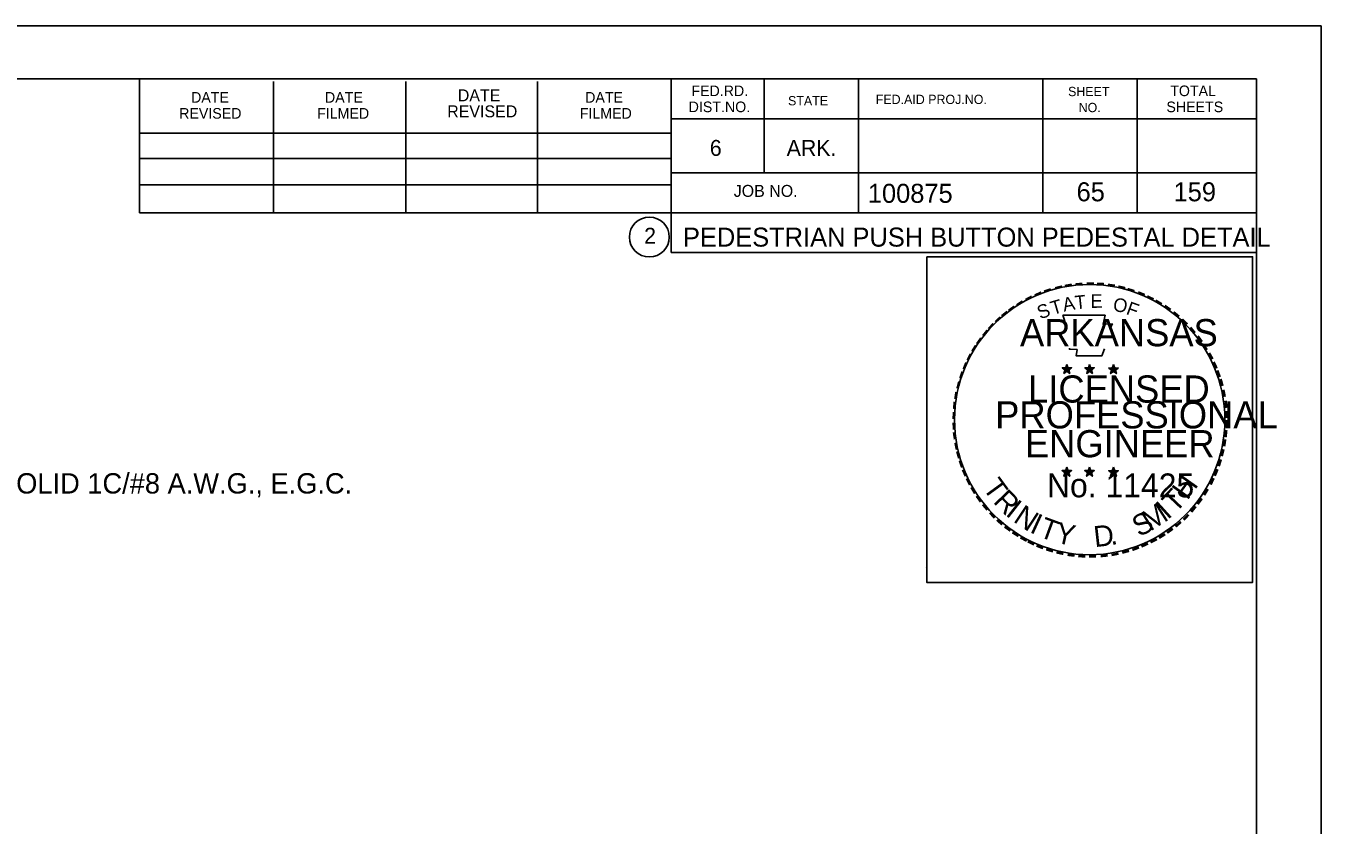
# Model space of a CAD drawing. Extents: x 1369885 to 1370886, y 379976 to 380616.
# Drawn here: x 1370599.4 to 1370885.5, y 380438.9 to 380615.6 of the extents above; entities that cross this region are included whole.
import ezdxf

# ---------------------------------------------------------------- set-up
doc = ezdxf.new("R2010")
doc.units = 0
for name, color, linetype in [('R_Border', 7, 'Continuous'), ('R_Border PE', 7, 'Continuous'), ('R_Draft', 7, 'Continuous'), ('R_No Plot', 7, 'Continuous')]:
    doc.layers.add(name, color=color, linetype=linetype)

msp = doc.modelspace()

# ---------------------------------------------------------------- linework, layer by layer
at = {"layer": 'R_Border'}
for p, q in [((1369922.71, 380603.9), (1370871.25, 380603.9)), ((1370624.47, 380574.26), (1370624.47, 380603.9)), ((1370654.05, 380574.26), (1370654.05, 380603.3)), ((1370683.33, 380574.26), (1370683.33, 380603.3)), ((1370712.37, 380574.26), (1370712.37, 380603.3)), ((1370741.95, 380603.9), (1370741.95, 380565.5)), ((1370762.47, 380603.9), (1370762.47, 380583.08)), ((1370783.29, 380603.9), (1370783.29, 380574.26)), ((1370824.03, 380603.9), (1370824.03, 380574.26)), ((1370844.85, 380603.9), (1370844.85, 380574.26)), ((1370871.25, 379987.52), (1370871.25, 380603.9)), ((1370871.25, 380595.08), (1370741.95, 380595.08)), ((1370871.25, 380595.14), (1370871.25, 380595.14)), ((1370624.47, 380591.84), (1370741.95, 380591.84)), ((1370624.47, 380586.26), (1370741.95, 380586.26)), ((1370871.25, 380583.08), (1370741.95, 380583.08)), ((1370750.83, 380583.08), (1370871.25, 380583.08)), ((1370624.47, 380574.26), (1370624.47, 380580.44)), ((1370624.47, 380580.44), (1370741.95, 380580.44)), ((1370871.25, 380574.26), (1370624.47, 380574.26)), ((1370741.95, 380565.5), (1370871.25, 380565.5))]:
    msp.add_line(p, q, dxfattribs=at)
msp.add_circle((1370737.11, 380568.91), 4.4, dxfattribs=at)
at = {"layer": 'R_Border PE'}
for p, q in [((1370828.31, 380540.01), (1370829.35, 380539.67)), ((1370828.31, 380540.01), (1370829.07, 380539.87)), ((1370828.31, 380540.01), (1370829.02, 380539.64)), ((1370828.71, 380538.78), (1370829.35, 380539.67)), ((1370828.71, 380538.78), (1370829.08, 380539.51)), ((1370828.71, 380538.78), (1370829.35, 380539.43)), ((1370829.35, 380540.77), (1370829.23, 380540.01)), ((1370829.35, 380539.67), (1370829.35, 380540.77)), ((1370829.35, 380540.77), (1370829.5, 380540.02)), ((1370830.39, 380540.01), (1370829.35, 380539.67)), ((1370829.99, 380538.78), (1370829.35, 380539.67)), ((1370829.99, 380538.78), (1370829.35, 380539.42)), ((1370830.39, 380540.01), (1370829.54, 380539.86)), ((1370829.99, 380538.78), (1370829.58, 380539.66)), ((1370830.39, 380540.01), (1370829.78, 380539.7)), ((1370833.32, 380540.01), (1370834.36, 380539.67)), ((1370833.32, 380540.01), (1370834.08, 380539.87)), ((1370833.32, 380540.01), (1370834.03, 380539.64)), ((1370833.72, 380538.78), (1370834.36, 380539.67)), ((1370833.72, 380538.78), (1370834.09, 380539.51)), ((1370833.72, 380538.78), (1370834.36, 380539.43)), ((1370834.36, 380540.77), (1370834.24, 380540.01)), ((1370834.36, 380539.67), (1370834.36, 380540.77)), ((1370834.36, 380540.77), (1370834.51, 380540.02)), ((1370835.4, 380540.01), (1370834.36, 380539.67)), ((1370835, 380538.78), (1370834.36, 380539.67)), ((1370835, 380538.78), (1370834.36, 380539.42)), ((1370835.4, 380540.01), (1370834.55, 380539.86)), ((1370835, 380538.78), (1370834.59, 380539.66)), ((1370835.4, 380540.01), (1370834.79, 380539.7)), ((1370838.61, 380539.97), (1370839.66, 380539.64)), ((1370838.61, 380539.97), (1370839.37, 380539.84)), ((1370838.61, 380539.97), (1370839.32, 380539.6)), ((1370839.01, 380538.75), (1370839.66, 380539.64)), ((1370839.01, 380538.75), (1370839.39, 380539.48)), ((1370839.01, 380538.75), (1370839.65, 380539.4)), ((1370839.66, 380540.73), (1370839.53, 380539.98)), ((1370840.29, 380538.75), (1370839.65, 380539.39)), ((1370839.66, 380539.64), (1370839.66, 380540.73)), ((1370839.66, 380540.73), (1370839.8, 380539.98)), ((1370840.7, 380539.97), (1370839.66, 380539.64)), ((1370840.29, 380538.75), (1370839.66, 380539.64)), ((1370840.7, 380539.97), (1370839.84, 380539.82)), ((1370840.29, 380538.75), (1370839.88, 380539.62)), ((1370840.7, 380539.97), (1370840.08, 380539.66)), ((1370828.29, 380517.29), (1370829.34, 380516.95)), ((1370828.29, 380517.29), (1370829.05, 380517.15)), ((1370828.29, 380517.29), (1370829.01, 380516.92)), ((1370828.69, 380516.06), (1370829.34, 380516.95)), ((1370828.69, 380516.06), (1370829.07, 380516.8)), ((1370828.69, 380516.06), (1370829.34, 380516.71)), ((1370829.34, 380518.05), (1370829.22, 380517.29)), ((1370829.34, 380516.95), (1370829.34, 380518.05)), ((1370829.34, 380518.05), (1370829.49, 380517.3)), ((1370830.38, 380517.29), (1370829.34, 380516.95)), ((1370829.98, 380516.06), (1370829.34, 380516.95)), ((1370829.98, 380516.06), (1370829.34, 380516.71)), ((1370830.38, 380517.29), (1370829.52, 380517.14)), ((1370829.98, 380516.06), (1370829.57, 380516.94)), ((1370830.38, 380517.29), (1370829.77, 380516.98)), ((1370833.3, 380517.29), (1370834.35, 380516.95)), ((1370833.3, 380517.29), (1370834.06, 380517.15)), ((1370833.3, 380517.29), (1370834.01, 380516.92)), ((1370833.7, 380516.06), (1370834.35, 380516.95)), ((1370833.7, 380516.06), (1370834.08, 380516.8)), ((1370833.7, 380516.06), (1370834.34, 380516.71)), ((1370834.35, 380518.05), (1370834.23, 380517.29)), ((1370834.99, 380516.06), (1370834.34, 380516.71)), ((1370834.35, 380516.95), (1370834.35, 380518.05)), ((1370834.35, 380518.05), (1370834.5, 380517.3)), ((1370835.39, 380517.29), (1370834.35, 380516.95)), ((1370834.99, 380516.06), (1370834.35, 380516.95)), ((1370835.39, 380517.29), (1370834.53, 380517.14)), ((1370834.99, 380516.06), (1370834.58, 380516.94)), ((1370835.39, 380517.29), (1370834.78, 380516.98)), ((1370838.6, 380517.26), (1370839.65, 380516.92)), ((1370838.6, 380517.26), (1370839.36, 380517.12)), ((1370838.6, 380517.26), (1370839.31, 380516.89)), ((1370839, 380516.03), (1370839.65, 380516.92)), ((1370839, 380516.03), (1370839.38, 380516.77)), ((1370839, 380516.03), (1370839.64, 380516.68)), ((1370839.65, 380518.02), (1370839.53, 380517.26)), ((1370840.29, 380516.03), (1370839.64, 380516.68)), ((1370839.65, 380516.92), (1370839.65, 380518.02)), ((1370839.65, 380518.02), (1370839.8, 380517.27)), ((1370840.69, 380517.26), (1370839.65, 380516.92)), ((1370840.29, 380516.03), (1370839.65, 380516.92)), ((1370840.69, 380517.26), (1370839.83, 380517.11)), ((1370840.29, 380516.03), (1370839.88, 380516.91)), ((1370840.69, 380517.26), (1370840.08, 380516.95))]:
    msp.add_line(p, q, dxfattribs=at)
for points in [[(1370828.43, 380551.64), (1370829.24, 380549.16)], [(1370838.96, 380548.87), (1370839.39, 380549.73), (1370837.33, 380549.65), (1370837.78, 380551.64), (1370828.43, 380551.64)], [(1370829.91, 380544.37), (1370829.91, 380544.11), (1370831.59, 380544.05), (1370831.43, 380542.63), (1370837.04, 380542.63), (1370837.65, 380544.24)], [(1370829.35, 380540.77), (1370829.99, 380538.78), (1370828.31, 380540.01), (1370830.39, 380540.01), (1370828.71, 380538.78), (1370829.35, 380540.77)], [(1370834.36, 380540.77), (1370835, 380538.78), (1370833.32, 380540.01), (1370835.4, 380540.01), (1370833.72, 380538.78), (1370834.36, 380540.77)], [(1370839.66, 380540.73), (1370840.29, 380538.75), (1370838.61, 380539.97), (1370840.7, 380539.97), (1370839.01, 380538.75), (1370839.66, 380540.73)], [(1370829.34, 380518.05), (1370829.98, 380516.06), (1370828.29, 380517.29), (1370830.38, 380517.29), (1370828.69, 380516.06), (1370829.34, 380518.05)], [(1370834.35, 380518.05), (1370834.99, 380516.06), (1370833.3, 380517.29), (1370835.39, 380517.29), (1370833.7, 380516.06), (1370834.35, 380518.05)], [(1370839.65, 380518.02), (1370840.29, 380516.03), (1370838.6, 380517.26), (1370840.69, 380517.26), (1370839, 380516.03), (1370839.65, 380518.02)]]:
    msp.add_lwpolyline(points, dxfattribs=at)
for centre, radius in [((1370829.35, 380539.67), 0.517), ((1370829.35, 380539.67), 0.434), ((1370829.35, 380539.67), 0.347), ((1370829.35, 380539.67), 0.297), ((1370829.35, 380539.67), 0.224), ((1370829.35, 380539.67), 0.149), ((1370829.35, 380539.67), 0.0889), ((1370834.36, 380539.67), 0.517), ((1370834.36, 380539.67), 0.434), ((1370834.36, 380539.67), 0.347), ((1370834.36, 380539.67), 0.297), ((1370834.36, 380539.67), 0.224), ((1370834.36, 380539.67), 0.149), ((1370834.36, 380539.67), 0.0889), ((1370839.65, 380539.64), 0.517), ((1370839.65, 380539.64), 0.434), ((1370839.65, 380539.64), 0.347), ((1370839.65, 380539.64), 0.297), ((1370839.65, 380539.64), 0.224), ((1370839.65, 380539.64), 0.149), ((1370839.65, 380539.64), 0.0889), ((1370829.34, 380516.95), 0.517), ((1370829.34, 380516.95), 0.434), ((1370829.34, 380516.95), 0.347), ((1370829.34, 380516.95), 0.297), ((1370829.34, 380516.95), 0.224), ((1370829.34, 380516.95), 0.149), ((1370829.34, 380516.95), 0.0889), ((1370834.35, 380516.95), 0.517), ((1370834.35, 380516.95), 0.434), ((1370834.35, 380516.95), 0.347), ((1370834.35, 380516.95), 0.297), ((1370834.35, 380516.95), 0.224), ((1370834.35, 380516.95), 0.149), ((1370834.35, 380516.95), 0.0889), ((1370839.65, 380516.92), 0.517), ((1370839.65, 380516.92), 0.434), ((1370839.65, 380516.92), 0.347), ((1370839.65, 380516.92), 0.297), ((1370839.65, 380516.92), 0.224), ((1370839.65, 380516.92), 0.149), ((1370839.65, 380516.92), 0.0889)]:
    msp.add_circle(centre, radius, dxfattribs=at)
at = {"layer": 'R_No Plot'}
for p, q in [((1369885.51, 380615.59), (1370885.51, 380615.59)), ((1370798.15, 380495.87), (1370798.15, 380495.87))]:
    msp.add_line(p, q, dxfattribs=at)
for points in [[(1369885.49, 380615.59), (1370885.51, 380615.59), (1370885.51, 379975.58), (1369885.49, 379975.58)], [(1370798.39, 380564.56), (1370870.39, 380564.56), (1370870.39, 380492.56), (1370798.39, 380492.56)]]:
    msp.add_lwpolyline(points, close=True, dxfattribs=at)
msp.add_circle((1370834.39, 380528.56), 29.86, dxfattribs=at)

# ---------------------------------------------------------------- texts
at = {"layer": 'R_Border'}
for s, height, p in [('DATE', 2.638, (1370694.79, 380598.92)), ('FED.RD.', 2.346, (1370746.39, 380600.06)), ('SHEET', 2.052, (1370829.61, 380600.06)), ('TOTAL', 2.346, (1370852.17, 380600.06)), ('DATE', 2.346, (1370635.87, 380598.62)), ('DATE', 2.346, (1370665.45, 380598.62)), ('DATE', 2.346, (1370722.93, 380598.62)), ('DIST.NO.', 2.346, (1370745.79, 380596.52)), ('STATE', 2.052, (1370767.75, 380598.02)), ('FED.AID PROJ.NO.', 2.052, (1370787.13, 380598.32)), ('NO.', 2.052, (1370831.95, 380596.52)), ('SHEETS', 2.346, (1370851.33, 380596.52)), ('REVISED', 2.346, (1370633.23, 380595.08)), ('FILMED', 2.346, (1370663.71, 380595.08)), ('REVISED', 2.638, (1370692.45, 380595.38)), ('FILMED', 2.346, (1370721.73, 380595.08)), ('6', 3.52, (1370750.47, 380586.86)), ('ARK.', 3.517, (1370767.45, 380586.86)), ('JOB NO.', 2.638, (1370755.75, 380577.8)), ('100875', 4.2, (1370785.38, 380576.48)), ('65', 4.2, (1370831.49, 380576.82)), ('159', 4.2, (1370852.92, 380576.82)), ('2', 3.52, (1370735.96, 380567.45)), ('PEDESTRIAN PUSH BUTTON PEDESTAL DETAIL', 4.2, (1370744.54, 380566.8))]:
    msp.add_text(s, height=height, dxfattribs=at).set_placement(p)
at = {"layer": 'R_Border PE'}
for s, height, rotation, p in [('-', 4.8, 10.2193, (1370828.96, 380556.23)), ('-', 4.8, 5.8968, (1370831.14, 380556.56)), ('-', 4.8, 0.1862, (1370833.46, 380556.78)), ('-', 4.8, 357.743, (1370835.63, 380556.74)), ('-', 4.8, 352.1617, (1370837.86, 380556.57)), ('-', 4.8, 28.7918, (1370820.87, 380553.26)), ('-', 4.8, 24.3072, (1370822.77, 380554.21)), ('-', 4.8, 19.1761, (1370824.67, 380555.02)), ('-', 4.8, 13.6302, (1370826.92, 380555.74)), ('A', 3, 11.2132, (1370828.71, 380552.42)), ('T', 3, 6.0228, (1370831.26, 380552.92)), ('E', 3, 0.8323, (1370834.58, 380553.25)), ('-', 4.8, 347.2049, (1370840.02, 380556.23)), ('-', 4.8, 342.3362, (1370841.92, 380555.76)), ('-', 4.8, 337.8551, (1370844.13, 380555.09)), ('-', 4.8, 334.1211, (1370846.02, 380554.28)), ('-', 4.8, 38.9507, (1370815.92, 380549.83)), ('-', 4.8, 36.2317, (1370817.35, 380550.97)), ('-', 4.8, 34.0636, (1370819.08, 380552.15)), ('S', 3, 21.594, (1370823.49, 380550.67)), ('T', 3, 16.4036, (1370826.24, 380551.67)), ('O', 3, 350.4515, (1370839.39, 380552.62)), ('F', 3, 340.0707, (1370842.25, 380551.93)), ('-', 4.8, 329.6409, (1370847.76, 380553.43)), ('-', 4.8, 325.8627, (1370849.69, 380552.35)), ('-', 4.8, 48.4231, (1370813.28, 380547.15)), ('-', 4.8, 42.9622, (1370814.62, 380548.58)), ('-', 4.8, 320.5297, (1370851.52, 380551.07)), ('-', 4.8, 315.5786, (1370853.31, 380549.61)), ('-', 4.8, 50.6142, (1370812.07, 380545.69)), ('-', 4.8, 309.8797, (1370855.02, 380547.96)), ('-', 4.8, 306.6522, (1370856.6, 380546.15)), ('-', 4.8, 58.0706, (1370809.85, 380542.41)), ('-', 4.8, 54.2325, (1370810.83, 380543.99)), ('-', 4.2, 303.6753, (1370858.05, 380544.45)), ('-', 4.8, 67.7743, (1370808.14, 380538.73)), ('-', 4.8, 62.8713, (1370808.91, 380540.57)), ('-', 4.8, 299.6684, (1370859.01, 380542.63)), ('-', 4.8, 294.6628, (1370859.98, 380540.79)), ('-', 4.8, 72.3945, (1370807.48, 380536.84)), ('-', 4.8, 290.5728, (1370860.75, 380539.06)), ('-', 4.8, 75.461, (1370806.89, 380534.7)), ('-', 4.8, 285.1233, (1370861.46, 380537.32)), ('-', 4.8, 81.2013, (1370806.49, 380532.56)), ('-', 4.8, 280.5493, (1370862.06, 380535.09)), ('-', 4.8, 276.5962, (1370862.54, 380532.79)), ('-', 4.8, 89.0622, (1370806.19, 380528.39)), ('-', 4.8, 85.1863, (1370806.26, 380530.49)), ('-', 4.8, 274.3301, (1370862.72, 380530.62)), ('-', 4.8, 94.1959, (1370806.29, 380526.21)), ('-', 4.8, 269.9407, (1370862.82, 380528.73)), ('-', 4.8, 98.9479, (1370806.51, 380524.21)), ('-', 4.8, 260.9953, (1370862.55, 380524.77)), ('-', 4.8, 263.5172, (1370862.77, 380526.73)), ('-', 4.8, 101.7149, (1370806.92, 380522.01)), ('-', 4.8, 105.4578, (1370807.4, 380520.23)), ('-', 4.8, 255.7626, (1370862.22, 380522.73)), ('-', 4.8, 109.0874, (1370808.05, 380518.33)), ('-', 4.8, 252.8681, (1370861.68, 380520.57)), ('-', 4.8, 114.0643, (1370808.81, 380516.55)), ('-', 4.8, 115.7289, (1370809.72, 380514.69)), ('T', 4.62, 306.0406, (1370810.62, 380513.47)), ('H', 4.62, 54.6088, (1370855.98, 380510.57)), ('-', 4.8, 244.6197, (1370860.23, 380516.67)), ('-', 4.8, 247.8887, (1370861.01, 380518.55)), ('-', 4.8, 120.4471, (1370810.79, 380512.93)), ('R', 4.62, 314.005, (1370812.91, 380510.33)), ('T', 4.62, 46.6444, (1370853.31, 380507.75)), ('-', 4.8, 239.0712, (1370859.04, 380514.41)), ('-', 4.8, 125.8934, (1370812, 380511.25)), ('-', 4.8, 130.7181, (1370813.39, 380509.6)), ('I', 4.62, 321.9694, (1370815.61, 380507.53)), ('M', 4.62, 32.6563, (1370847.77, 380503.77)), ('I', 4.62, 42.1136, (1370851.63, 380506.31)), ('-', 4.8, 233.8452, (1370857.84, 380512.45)), ('-', 4.8, 134.2238, (1370814.94, 380507.96)), ('N', 4.62, 326.5002, (1370817.31, 380506.11)), ('I', 4.62, 335.3603, (1370820.94, 380503.76)), ('T', 4.62, 339.8912, (1370822.92, 380502.77)), ('S', 4.62, 26.9312, (1370845.26, 380502.55)), ('-', 4.8, 225.7653, (1370855.11, 380509.06)), ('-', 4.8, 231.2538, (1370856.55, 380510.75)), ('-', 4.8, 138.9338, (1370816.52, 380506.57)), ('-', 4.8, 144.6463, (1370818.18, 380505.35)), ('Y', 4.62, 347.8556, (1370826.57, 380501.44)), ('D', 4.62, 6.3969, (1370835.52, 380500.36)), ('-', 4.8, 215.7363, (1370851.9, 380506.12)), ('-', 4.8, 221.0851, (1370853.54, 380507.53)), ('-', 4.8, 148.0898, (1370819.87, 380504.24)), ('-', 4.8, 151.5704, (1370821.6, 380503.26)), ('-', 4.8, 154.6002, (1370823.17, 380502.52)), ('.', 4.62, 13.7642, (1370839.1, 380500.75)), ('-', 4.8, 204.2516, (1370846.75, 380502.96)), ('-', 4.8, 207.3568, (1370848.62, 380503.92)), ('-', 4.8, 212.2491, (1370850.3, 380504.96)), ('-', 4.8, 158.5612, (1370825.04, 380501.76)), ('-', 4.8, 162.7983, (1370827.1, 380501.12)), ('-', 4.8, 167.5555, (1370829.25, 380500.63)), ('-', 4.8, 173.1155, (1370831.56, 380500.3)), ('-', 4.8, 176.5183, (1370833.81, 380500.14)), ('-', 4.8, 181.5918, (1370836.04, 380500.2)), ('-', 4.8, 185.8167, (1370838.47, 380500.42)), ('-', 4.8, 191.2858, (1370840.67, 380500.82)), ('-', 4.8, 195.4743, (1370842.86, 380501.42)), ('-', 4.8, 200.7184, (1370844.89, 380502.14))]:
    msp.add_text(s, height=height, rotation=rotation, dxfattribs=at).set_placement(p)
for s, height, p in [('ARKANSAS', 6, (1370818.99, 380544.78)), ('LICENSED', 6, (1370820.78, 380532.33)), ('DWB', 0.03, (1370829.31, 380539.66)), ('DWB', 0.03, (1370834.32, 380539.66)), ('DWB', 0.03, (1370839.62, 380539.63)), ('PROFESSIONAL', 6, (1370813.51, 380526.62)), ('ENGINEER', 6, (1370820.07, 380520.24)), ('No. 11425', 5.271, (1370824.95, 380511.39)), ('DWB', 0.03, (1370829.3, 380516.94)), ('DWB', 0.03, (1370834.31, 380516.94)), ('DWB', 0.03, (1370839.61, 380516.91))]:
    msp.add_text(s, height=height, dxfattribs=at).set_placement(p)
at = {"layer": 'R_Draft'}
msp.add_text(' 1/2" NMC WITH A SOLID 1C/#8 A.W.G., E.G.C.', height=4.5, dxfattribs=at).set_placement((1370541.27, 380512.22))

doc.saveas('drawing.dxf')
